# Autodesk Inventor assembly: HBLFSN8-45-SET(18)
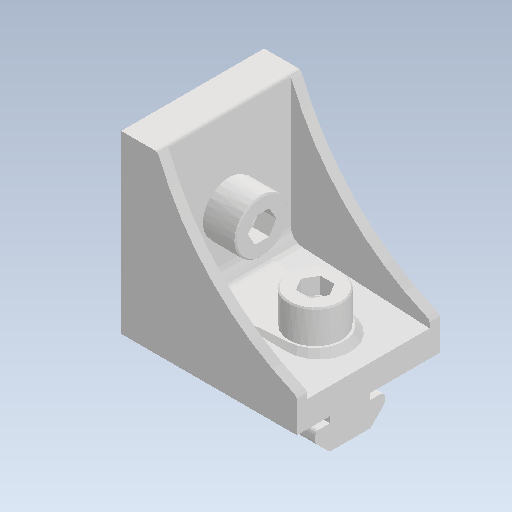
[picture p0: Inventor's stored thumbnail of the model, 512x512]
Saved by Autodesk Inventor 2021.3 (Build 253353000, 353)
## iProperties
Created: 2022-02
Part Number: HBLFSN8-45-SET(18)
Document SubType Name: Assembly
Designer: kengo
Author: kengo
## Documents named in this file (4)
- C:\Users\kengo\Documents\S2S_frame\SDC345\frame_misumi_ver12\HBLFSN8-45-SET(18).iam
- C:\Users\kengo\Documents\S2S_frame\SDC345\frame_misumi_ver12\HBLFSN8-45.ipt
- C:\Users\kengo\Documents\S2S_frame\SDC345\frame_misumi_ver12\HNTT8-8.ipt
- C:\Users\kengo\Documents\S2S_frame\SDC345\frame_misumi_ver12\CBM8-20.ipt
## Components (5 placed, 3 different names)
1. HBLFSN8-45
2. HNTT8-8
3. CBM8-20
4. HNTT8-8:1
5. CBM8-20:1
